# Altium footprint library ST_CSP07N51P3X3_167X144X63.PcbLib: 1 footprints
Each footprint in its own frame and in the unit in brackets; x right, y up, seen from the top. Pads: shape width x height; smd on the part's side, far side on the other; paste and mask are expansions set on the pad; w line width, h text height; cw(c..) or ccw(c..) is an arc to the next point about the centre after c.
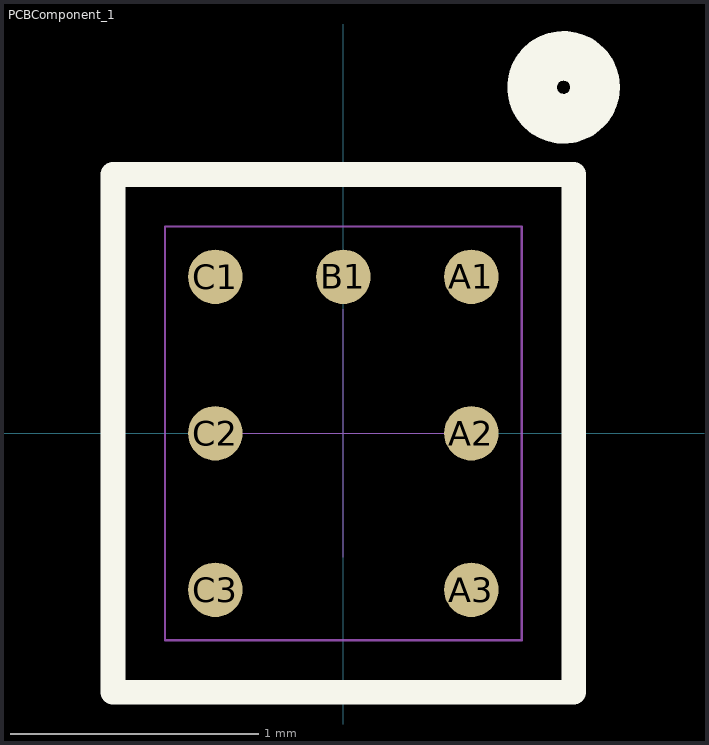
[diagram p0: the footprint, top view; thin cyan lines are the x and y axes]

## PCBComponent_1 [mm]
pads (7):
  round 0.22 smd paste-20 mask+0.05: A1(0.517,0.632) A2(0.517,0) A3(0.517,-0.632) B1(0,0.632) C1(-0.517,0.632) C2(-0.517,0) C3(-0.517,-0.632)
Top Overlay:
  circle w0.2: c0.889,1.397 r0.127
  lines w0.1: -0.93,-1.045 -0.93,1.045 0.93,1.045 0.93,-1.045 -0.93,-1.045
Top Paste:
  rectangle: 0.407,-0.742 0.627,-0.522
  rectangle: -0.627,-0.742 -0.407,-0.522
  rectangle: 0.407,-0.11 0.627,0.11
  rectangle: -0.627,-0.11 -0.407,0.11
  rectangle: 0.407,0.522 0.627,0.742
  rectangle: -0.11,0.522 0.11,0.742
  rectangle: -0.627,0.522 -0.407,0.742
Mechanical 15:
  lines w0.001: -0.5,0 0.5,0 ; 0,-0.5 0,0.5
  lines w0.01: -0.72,-0.835 -0.72,0.835 0.72,0.835 0.72,-0.835 -0.72,-0.835
3D body: height 0.63, standoff 0.2, extent -0.72,-0.835 0.72,0.835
